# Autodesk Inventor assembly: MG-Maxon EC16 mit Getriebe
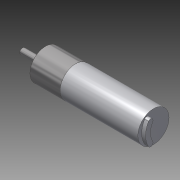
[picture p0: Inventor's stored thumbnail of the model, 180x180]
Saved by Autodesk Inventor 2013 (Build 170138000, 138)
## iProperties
Created: 2012-07
Part Number: MG-Maxon EC16 mit Getriebe
Document SubType Name: Assembly
Designer: rYan
Mass: 63.1528 g
Surface Area: 40.0165 cm^2
Volume: 11.4146 cm^3
Density: 5.53265 g/cm^3
Author: rYan
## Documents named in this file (3)
- D:\SVN\2013\Inventor\Dribbling Device\MG-Maxon EC16 mit Getriebe.iam
- D:\SVN\2013\Inventor\Kaufteile\MaxonEC16-30W.ipt
- D:\SVN\2013\Inventor\Kaufteile\Planetengetriebe GP 16 A.ipt
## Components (2 placed, 2 different names)
1. MaxonEC16-30W:1 — Passend:1, Passend:2, Passend:3
2. Planetengetriebe GP 16 A:1 — Passend:1, Passend:2, Passend:3
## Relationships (3: Mate 3)
- Passend:1 [Mate]: MaxonEC16-30W:1 ↔ Planetengetriebe GP 16 A:1
- Passend:2 [Mate]: MaxonEC16-30W:1 ↔ Planetengetriebe GP 16 A:1
- Passend:3 [Mate]: MaxonEC16-30W:1 ↔ Planetengetriebe GP 16 A:1
